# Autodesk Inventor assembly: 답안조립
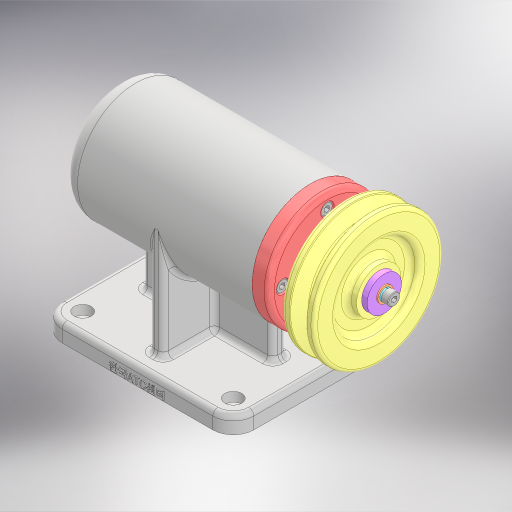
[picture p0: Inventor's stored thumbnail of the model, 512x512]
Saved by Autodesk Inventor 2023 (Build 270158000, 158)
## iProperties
Created: 2026-08
Part Number: 답안조립
Document SubType Name: Assembly
Designer: home
Author: home
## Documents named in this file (14)
- C:\Users\home\Desktop\760803V1008\답안조립.iam
- C:\Users\home\Desktop\760803V1008\본체.ipt
- C:\Users\home\Desktop\760803V1008\6각 구멍붙이 볼트 M4x12.ipt
- C:\Users\home\Desktop\760803V1008\V 벨트 풀리.ipt
- C:\Users\home\Desktop\760803V1008\깊은 홈 볼 베어링 6004.ipt
- C:\Users\home\Desktop\760803V1008\스러스트 볼 베어링 51202.ipt
- C:\Users\home\Desktop\760803V1008\스프링 와셔 M4.ipt
- C:\Users\home\Desktop\760803V1008\어댑터 슬리브.ipt
- C:\Users\home\Desktop\760803V1008\엔드 캡.ipt
- C:\Users\home\Desktop\760803V1008\오일 실 20 32 5.ipt
- C:\Users\home\Desktop\760803V1008\축.ipt
- C:\Users\home\Desktop\760803V1008\커버.ipt
- C:\Users\home\Desktop\760803V1008\평 와셔 M4.ipt
- C:\Users\home\Desktop\760803V1008\평행 키 5x5x16.ipt
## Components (7 placed, 2 different names)
1. 6각 구멍붙이 볼트 M4x12:1
2. V 벨트 풀리:1
3. 6각 구멍붙이 볼트 M4x12:2
4. 6각 구멍붙이 볼트 M4x12:3
5. 6각 구멍붙이 볼트 M4x12:4
6. 6각 구멍붙이 볼트 M4x12:5
7. 6각 구멍붙이 볼트 M4x12:6
